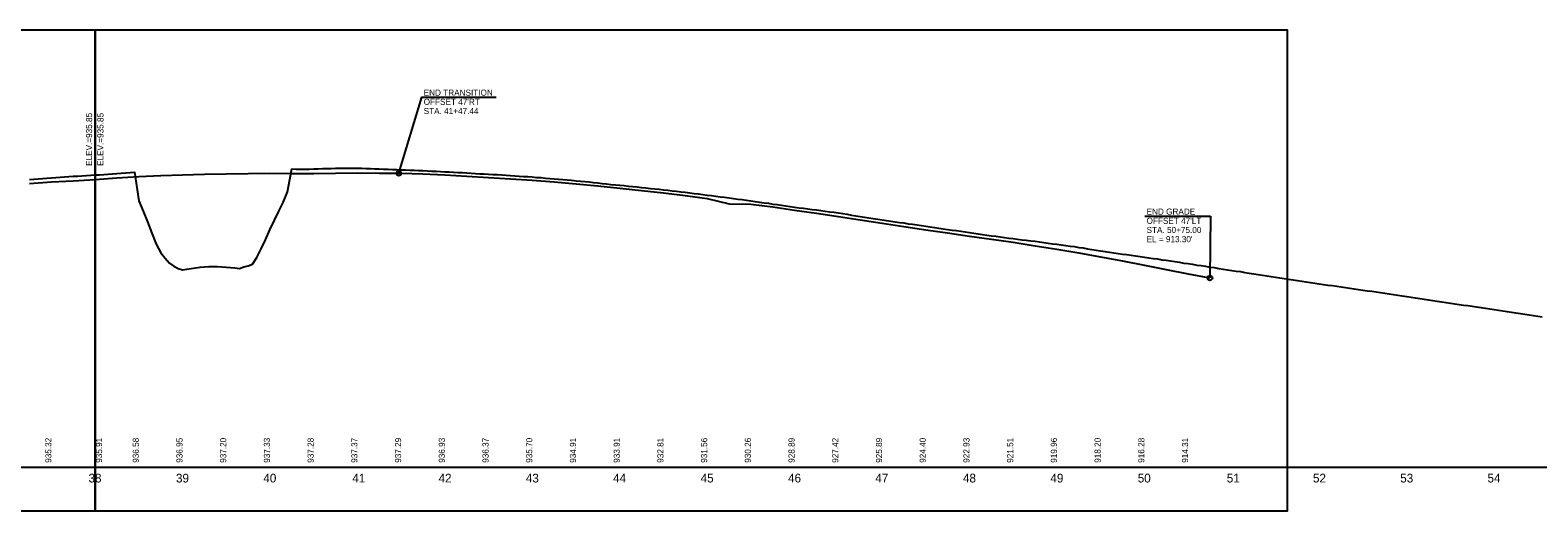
# Model space of a CAD drawing. Extents: x 1640737 to 1656943, y 755266 to 852516.
# Drawn here: x 1650105 to 1651829, y 845216 to 845766 of the extents above; entities that cross this region are included whole.
import ezdxf

# ---------------------------------------------------------------- set-up
doc = ezdxf.new("R2010")
doc.units = 0
for name, color, linetype in [('Exist Structure Minor Pipes CMP 12 Inch Text', 7, 'Continuous'), ('Exist Structure Minor Pipes RCP 18 Inch Text', 7, 'Continuous'), ('Exist Structure Minor Pipes RCP 24 Inch Text', 7, 'Continuous'), ('Exist Structure Minor Pipes RCP 30 Inch Text', 7, 'Continuous'), ('Exist Structure Minor Pipes RCP 36 Inch Text', 7, 'Continuous'), ('Exist Structure Minor Storm Sewer Manhole CELL', 7, 'Continuous'), ('Exist Utilities Sanitary Sewer Manhole CELL', 7, 'Continuous'), ('Raster_Level_0', 7, 'Continuous')]:
    doc.layers.add(name, color=color, linetype=linetype)

msp = doc.modelspace()

# ---------------------------------------------------------------- linework, layer by layer
at = {"layer": 'Exist Structure Minor Pipes CMP 12 Inch Text'}
for p, q in [((1651379.8, 845553.1), (1651454.8, 845553.1)), ((1651454.8, 845553.1), (1651454.3, 845482.5))]:
    msp.add_line(p, q, dxfattribs=at)
msp.add_lwpolyline([(1650526.7, 845602.2), (1650552.9, 845689.2), (1650637.9, 845689.2)], dxfattribs=at)
for centre in [(1650526.7, 845602.2), (1651454.3, 845482.5)]:
    msp.add_circle(centre, 2.75, dxfattribs=at)
at = {"layer": 'Exist Structure Minor Pipes RCP 30 Inch Text'}
for points in [[(1649015.5, 845216), (1650179.3, 845216), (1650179.3, 845766), (1649015.5, 845766)], [(1650179.3, 845216), (1651543, 845216), (1651543, 845766), (1650179.3, 845766)]]:
    msp.add_lwpolyline(points, close=True, dxfattribs=at)
at = {"layer": 'Exist Structure Minor Pipes RCP 36 Inch Text'}
msp.add_lwpolyline([(1650104.3, 845590.6), (1650129.3, 845592.3), (1650154.3, 845593.8), (1650179.3, 845595.3), (1650204.3, 845596.9), (1650229.3, 845598.6), (1650254.3, 845599.6), (1650279.3, 845600.5), (1650304.3, 845601.2), (1650329.3, 845601.7), (1650354.3, 845602.1), (1650379.3, 845602.4), (1650404.3, 845602.1), (1650429.3, 845602.1), (1650454.3, 845602.4), (1650479.3, 845602.6), (1650504.3, 845602.5), (1650529.3, 845602.2), (1650554.3, 845601.5), (1650579.3, 845600.4), (1650604.3, 845599.1), (1650629.3, 845597.6), (1650654.3, 845596), (1650679.3, 845594.2), (1650704.3, 845592.3), (1650729.3, 845590.3), (1650754.3, 845587.9), (1650779.3, 845585.3), (1650804.3, 845582.5), (1650829.3, 845579.8), (1650854.3, 845576.7), (1650879.3, 845573.5), (1650904.3, 845567.4), (1650929.3, 845567), (1650954.3, 845563.7), (1650979.3, 845560.2), (1651004.3, 845556.6), (1651029.3, 845552.8), (1651054.3, 845549), (1651079.3, 845545.2), (1651104.3, 845541.5), (1651129.3, 845537.7), (1651154.3, 845534.1), (1651179.3, 845530.4), (1651204.3, 845526.8), (1651229.3, 845523.3), (1651254.3, 845519.4), (1651279.3, 845515.5), (1651304.3, 845511.3), (1651329.3, 845506.7), (1651354.3, 845501.9), (1651379.3, 845497.1), (1651404.3, 845492.2), (1651429.3, 845487.3), (1651454.3, 845482.5)], dxfattribs=at)
at = {"layer": 'Exist Structure Minor Storm Sewer Manhole CELL'}
for points in [[(1650104.3, 845595.3), (1650109.3, 845595.4), (1650114.3, 845595.8), (1650119.3, 845596.2), (1650124.3, 845596.6), (1650129.3, 845597.1), (1650134.3, 845597.5), (1650139.3, 845597.8), (1650144.3, 845598.1), (1650149.3, 845598.5), (1650154.3, 845598.8), (1650159.3, 845599.1), (1650164.3, 845599.4), (1650169.3, 845599.8), (1650174.3, 845600), (1650179.3, 845600.3), (1650184.3, 845600.6), (1650189.3, 845600.9), (1650194.3, 845601.2), (1650199.3, 845601.6), (1650204.3, 845602), (1650209.3, 845602.3), (1650214.3, 845602.8), (1650219.3, 845603), (1650224.3, 845603.4), (1650229.3, 845570.9), (1650234.3, 845558.9), (1650239.3, 845546.6), (1650244.3, 845533.9), (1650249.3, 845521.2), (1650254.3, 845511.1), (1650259.3, 845505.3), (1650264.3, 845499.4), (1650269.3, 845496), (1650274.3, 845493.5), (1650279.3, 845491.9), (1650284.3, 845492.6), (1650289.3, 845493.2), (1650294.3, 845493.9), (1650299.3, 845494.7), (1650304.3, 845495.2), (1650309.3, 845495.7), (1650314.3, 845495.7), (1650319.3, 845495.6), (1650324.3, 845495.3), (1650329.3, 845495), (1650334.3, 845494.5), (1650339.3, 845494.1), (1650344.3, 845493.5), (1650349.3, 845495.1), (1650354.3, 845496.3), (1650359.3, 845498.2), (1650364.3, 845506), (1650369.3, 845515.7), (1650374.3, 845526.3), (1650379.3, 845537.6), (1650384.3, 845548.8), (1650389.3, 845558.9), (1650394.3, 845568.8), (1650399.3, 845581.1), (1650404.3, 845607.2), (1650409.3, 845607.1), (1650414.3, 845607), (1650419.3, 845606.9), (1650424.3, 845607.1), (1650429.3, 845607.2), (1650434.3, 845607.4), (1650439.3, 845607.6), (1650444.3, 845607.8), (1650449.3, 845607.9), (1650454.3, 845608.1), (1650459.3, 845608.1), (1650464.3, 845608.2), (1650469.3, 845608.2), (1650474.3, 845608.1), (1650479.3, 845608), (1650484.3, 845608), (1650489.3, 845607.8), (1650494.3, 845607.6), (1650499.3, 845607.4), (1650504.3, 845607.2), (1650509.3, 845607), (1650514.3, 845606.8), (1650519.3, 845606.6), (1650524.3, 845606.5), (1650529.3, 845606.3), (1650534.3, 845606.1), (1650539.3, 845605.9), (1650544.3, 845605.7), (1650549.3, 845605.5), (1650554.3, 845605.3), (1650559.3, 845605.1), (1650564.3, 845604.8), (1650569.3, 845604.6), (1650574.3, 845604.4), (1650579.3, 845604.1)], [(1650579.3, 845604.1), (1650584.3, 845603.9), (1650589.3, 845603.6), (1650594.3, 845603.3), (1650599.3, 845603), (1650604.3, 845602.7), (1650609.3, 845602.4), (1650614.3, 845602.1), (1650619.3, 845601.8), (1650624.3, 845601.5), (1650629.3, 845601.3), (1650634.3, 845601), (1650639.3, 845600.7), (1650644.3, 845600.4), (1650649.3, 845600), (1650654.3, 845599.7), (1650659.3, 845599.4), (1650664.3, 845599.1), (1650669.3, 845598.7), (1650674.3, 845598.4), (1650679.3, 845598), (1650684.3, 845597.6), (1650689.3, 845597.3), (1650694.3, 845596.8), (1650699.3, 845596.4), (1650704.3, 845596), (1650709.3, 845595.6), (1650714.3, 845595.2), (1650719.3, 845594.7), (1650724.3, 845594.3), (1650729.3, 845593.8), (1650734.3, 845593.3), (1650739.3, 845592.9), (1650744.3, 845592.4), (1650749.3, 845591.8), (1650754.3, 845591.2), (1650759.3, 845590.7), (1650764.3, 845590.1), (1650769.3, 845589.5), (1650774.3, 845589), (1650779.3, 845588.5), (1650784.3, 845588.1), (1650789.3, 845587.6), (1650794.3, 845587.1), (1650799.3, 845586.6), (1650804.3, 845586.1), (1650809.3, 845585.6), (1650814.3, 845585), (1650819.3, 845584.5), (1650824.3, 845584), (1650829.3, 845583.4), (1650834.3, 845582.8), (1650839.3, 845582.2), (1650844.3, 845581.6), (1650849.3, 845581.1), (1650854.3, 845580.5), (1650859.3, 845579.9), (1650864.3, 845579.3), (1650869.3, 845578.6), (1650874.3, 845578), (1650879.3, 845577.4), (1650884.3, 845576.7), (1650889.3, 845576.1), (1650894.3, 845575.4), (1650899.3, 845574.8), (1650904.3, 845574.1), (1650909.3, 845573.5), (1650914.3, 845572.8), (1650919.3, 845572.1), (1650924.3, 845571.4), (1650929.3, 845570.7), (1650934.3, 845570), (1650939.3, 845569.3), (1650944.3, 845568.6), (1650949.3, 845567.9), (1650954.3, 845567.1), (1650959.3, 845566.4), (1650964.3, 845565.7), (1650969.3, 845564.9), (1650974.3, 845564.2), (1650979.3, 845563.6), (1650984.3, 845562.9), (1650989.3, 845562.2), (1650994.3, 845561.6), (1650999.3, 845560.9), (1651004.3, 845560.3), (1651009.3, 845559.6), (1651014.3, 845558.9), (1651019.3, 845558.2), (1651024.3, 845557.6), (1651029.3, 845556.9), (1651034.3, 845556.2), (1651039.3, 845555.4), (1651044.3, 845554.5), (1651049.3, 845553.7), (1651054.3, 845552.9), (1651059.3, 845552.1), (1651064.3, 845551.4), (1651069.3, 845550.6), (1651074.3, 845549.8), (1651079.3, 845549.1)], [(1651079.3, 845549.1), (1651084.3, 845548.3), (1651089.3, 845547.6), (1651094.3, 845546.8), (1651099.3, 845546.1), (1651104.3, 845545.4), (1651109.3, 845544.6), (1651114.3, 845543.9), (1651119.3, 845543.2), (1651124.3, 845542.4), (1651129.3, 845541.7), (1651134.3, 845541), (1651139.3, 845540.2), (1651144.3, 845539.5), (1651149.3, 845538.8), (1651154.3, 845538.1), (1651159.3, 845537.3), (1651164.3, 845536.6), (1651169.3, 845535.9), (1651174.3, 845535.1), (1651179.3, 845534.4), (1651184.3, 845533.7), (1651189.3, 845532.9), (1651194.3, 845532.2), (1651199.3, 845531.5), (1651204.3, 845530.8), (1651209.3, 845530.2), (1651214.3, 845529.5), (1651219.3, 845528.8), (1651224.3, 845528.1), (1651229.3, 845527.5), (1651234.3, 845526.9), (1651239.3, 845526.3), (1651244.3, 845525.7), (1651249.3, 845525), (1651254.3, 845524.4), (1651259.3, 845523.7), (1651264.3, 845523), (1651269.3, 845522.3), (1651274.3, 845521.6), (1651279.3, 845521), (1651284.3, 845520.3), (1651289.3, 845519.6), (1651294.3, 845519), (1651299.3, 845518.3), (1651304.3, 845517.5), (1651309.3, 845516.8), (1651314.3, 845516), (1651319.3, 845515.2), (1651324.3, 845514.4), (1651329.3, 845513.7), (1651334.3, 845512.9), (1651339.3, 845512.1), (1651344.3, 845511.4), (1651349.3, 845510.6), (1651354.3, 845509.9), (1651359.3, 845509.2), (1651364.3, 845508.5), (1651369.3, 845507.8), (1651374.3, 845507.1), (1651379.3, 845506.4), (1651384.3, 845505.7), (1651389.3, 845504.9), (1651394.3, 845504.2), (1651399.3, 845503.4), (1651404.3, 845502.7), (1651409.3, 845501.9), (1651414.3, 845501.2), (1651419.3, 845500.4), (1651424.3, 845499.6), (1651429.3, 845498.9), (1651434.3, 845498.1), (1651439.3, 845497.3), (1651444.3, 845496.6), (1651449.3, 845495.8), (1651454.3, 845495), (1651459.3, 845494.3), (1651464.3, 845493.5), (1651469.3, 845492.7), (1651474.3, 845491.9), (1651479.3, 845491.2), (1651484.3, 845490.4), (1651489.3, 845489.7), (1651494.3, 845488.9), (1651499.3, 845488.1), (1651504.3, 845487.3), (1651509.3, 845486.5), (1651514.3, 845485.7), (1651519.3, 845485), (1651524.3, 845484.2), (1651529.3, 845483.5), (1651534.3, 845482.7), (1651539.3, 845481.9), (1651544.3, 845481.1), (1651549.3, 845480.3), (1651554.3, 845479.5), (1651559.3, 845478.7), (1651564.3, 845478), (1651569.3, 845477.2), (1651574.3, 845476.5), (1651579.3, 845475.7)], [(1651579.3, 845475.7), (1651584.3, 845475), (1651589.3, 845474.3), (1651594.3, 845473.7), (1651599.3, 845473), (1651604.3, 845472.3), (1651609.3, 845471.6), (1651614.3, 845470.8), (1651619.3, 845470.1), (1651624.3, 845469.4), (1651629.3, 845468.6), (1651634.3, 845467.9), (1651639.3, 845467.2), (1651644.3, 845466.5), (1651649.3, 845465.8), (1651654.3, 845465.1), (1651659.3, 845464.3), (1651664.3, 845463.5), (1651669.3, 845462.7), (1651674.3, 845462), (1651679.3, 845461.2), (1651684.3, 845460.5), (1651689.3, 845459.8), (1651694.3, 845459), (1651699.3, 845458.2), (1651704.3, 845457.4), (1651709.3, 845456.6), (1651714.3, 845455.8), (1651719.3, 845455.1), (1651724.3, 845454.3), (1651729.3, 845453.5), (1651734.3, 845452.9), (1651739.3, 845452.2), (1651744.3, 845451.5), (1651749.3, 845450.8), (1651754.3, 845450.2), (1651759.3, 845449.4), (1651764.3, 845448.6), (1651769.3, 845447.8), (1651774.3, 845447), (1651779.3, 845446.3), (1651784.3, 845445.6), (1651789.3, 845444.8), (1651794.3, 845444), (1651799.3, 845443.3), (1651804.3, 845442.5), (1651809.3, 845441.8), (1651814.3, 845441.1), (1651819.3, 845440.3), (1651824.3, 845439.5), (1651829.3, 845438.7), (1651834.3, 845438)]]:
    msp.add_lwpolyline(points, dxfattribs=at)
at = {"layer": 'Raster_Level_0'}
msp.add_line((1649079.3, 845266), (1655379.3, 845266), dxfattribs=at)

# ---------------------------------------------------------------- texts
at = {"layer": 'Exist Structure Minor Pipes CMP 12 Inch Text'}
for s, p in [('END TRANSITION', (1650555.1, 845691)), ("OFFSET 47'RT", (1650555.1, 845680.5)), ('STA. 41+47.44', (1650555.1, 845670)), ('END GRADE', (1651381.8, 845554.9)), ("OFFSET 47'LT", (1651381.8, 845544.4)), ('STA. 50+75.00', (1651381.8, 845533.9)), ("EL = 913.30'", (1651381.8, 845523.4))]:
    msp.add_text(s, height=7, dxfattribs=at).set_placement(p)
at = {"layer": 'Exist Structure Minor Pipes RCP 18 Inch Text'}
for p in [(1650175.9, 845610.7), (1650188.9, 845610.7)]:
    msp.add_text('ELEV.=935.85', height=7, rotation=90, dxfattribs=at).set_placement(p)
at = {"layer": 'Exist Structure Minor Pipes RCP 24 Inch Text'}
for s, p in [('935.32', (1650129.3, 845271)), ('935.91', (1650187.3, 845271)), ('936.58', (1650229.3, 845271)), ('936.95', (1650279.3, 845271)), ('937.20', (1650329.3, 845271)), ('937.33', (1650379.3, 845271)), ('937.28', (1650429.3, 845271)), ('937.37', (1650479.3, 845271)), ('937.29', (1650529.3, 845271)), ('936.93', (1650579.3, 845271)), ('936.37', (1650629.3, 845271)), ('935.70', (1650679.3, 845271)), ('934.91', (1650729.3, 845271)), ('933.91', (1650779.3, 845271)), ('932.81', (1650829.3, 845271)), ('931.56', (1650879.3, 845271)), ('930.26', (1650929.3, 845271)), ('928.89', (1650979.3, 845271)), ('927.42', (1651029.3, 845271)), ('925.89', (1651079.3, 845271)), ('924.40', (1651129.3, 845271)), ('922.93', (1651179.3, 845271)), ('921.51', (1651229.3, 845271)), ('919.96', (1651279.3, 845271)), ('918.20', (1651329.3, 845271)), ('916.28', (1651379.3, 845271)), ('914.31', (1651429.3, 845271))]:
    msp.add_text(s, height=7, rotation=90, dxfattribs=at).set_placement(p)
at = {"layer": 'Exist Utilities Sanitary Sewer Manhole CELL'}
for s, p in [('38', (1650171.8, 845248.5)), ('39', (1650271.8, 845248.5)), ('40', (1650371.7, 845248.5)), ('41', (1650473.5, 845248.5)), ('42', (1650572.1, 845248.5)), ('43', (1650671.9, 845248.5)), ('44', (1650771.7, 845248.5)), ('45', (1650871.8, 845248.5)), ('46', (1650971.8, 845248.5)), ('47', (1651071.6, 845248.5)), ('48', (1651171.8, 845248.5)), ('49', (1651271.8, 845248.5)), ('50', (1651371.7, 845248.5)), ('51', (1651473.5, 845248.5)), ('52', (1651572.1, 845248.5)), ('53', (1651671.9, 845248.5)), ('54', (1651771.7, 845248.5))]:
    msp.add_text(s, height=10, dxfattribs=at).set_placement(p)

doc.saveas('drawing.dxf')
